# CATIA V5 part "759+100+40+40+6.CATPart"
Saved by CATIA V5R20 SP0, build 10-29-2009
Part number: 759+100+40+40+6
Revision: TUTTO
Definition: NON CONOSCIUTO
Nomenclature: 759+100+40+40+6
Source: Unknown
Bounding box of the stored display mesh (mm): x -50 to 50, y -20 to 20, z 0 to 40
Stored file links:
  C:\Users\Utente\Desktop\IO LAVORO\3D X SITO CF\X 3D SITO CF 27-09-2020\759\759+100+40+40+6.CATPart
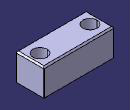
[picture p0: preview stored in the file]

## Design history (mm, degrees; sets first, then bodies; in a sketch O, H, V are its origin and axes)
Body1 "Smusso4" (main body)
  Solid1: solid without history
